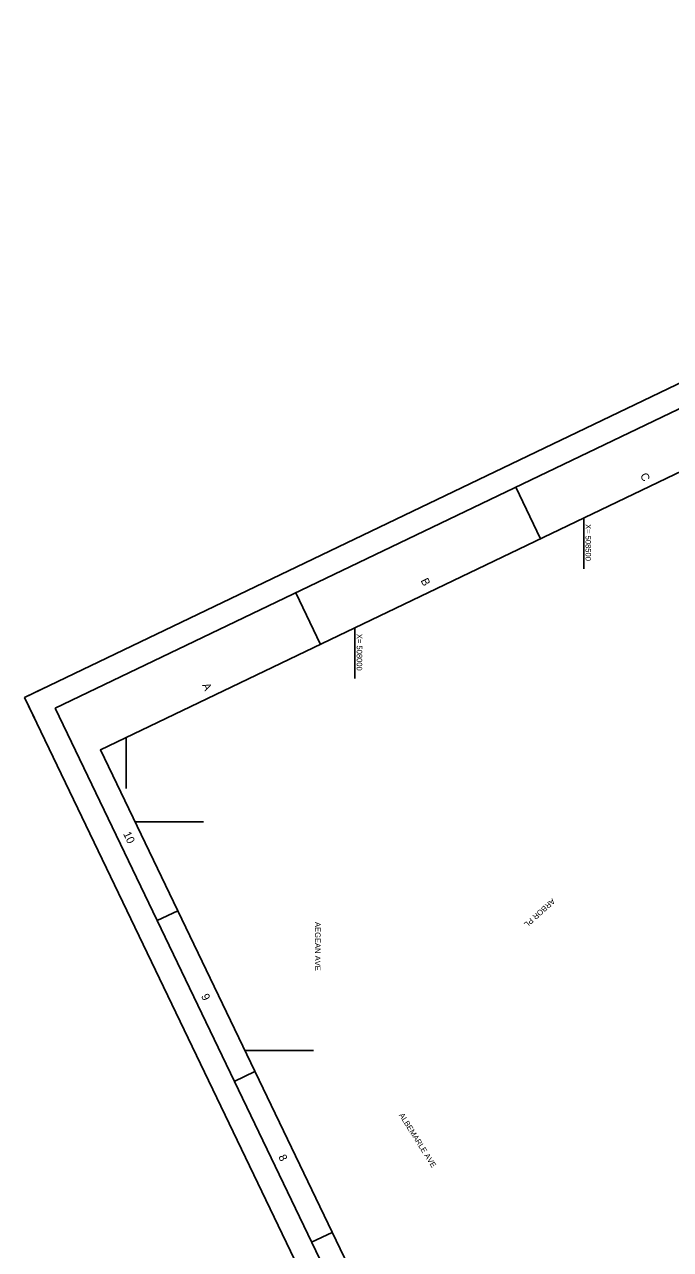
# Model space of a CAD drawing. Extents: x 507278 to 512248, y 1305805 to 1311243.
# Drawn here: x 507278 to 508690, y 1308565 to 1311243 of the extents above; entities that cross this region are included whole.
import ezdxf

# ---------------------------------------------------------------- set-up
doc = ezdxf.new("R2010")
doc.units = 0
for name, color, linetype in [('G-ANNO-NPLT', 7, 'Continuous'), ('G-ANNO-TTLB', 7, 'Continuous'), ('V-ROAD-IDEN', 7, 'Continuous'), ('V-TOPO-COOR-STAT', 7, 'Continuous')]:
    doc.layers.add(name, color=color, linetype=linetype)

msp = doc.modelspace()

# ---------------------------------------------------------------- linework, layer by layer
at = {"layer": 'G-ANNO-NPLT'}
msp.add_lwpolyline([(510343.2, 1311243.3), (512247.6, 1307276.8), (509182.6, 1305805.3), (507278.2, 1309771.7)], close=True, dxfattribs=at)
msp.add_lwpolyline([(507323.3, 1309793.4), (507278.2, 1309771.7), (507299.8, 1309726.7)], dxfattribs=at)
at = {"layer": 'G-ANNO-TTLB'}
for p, q in [((508351.5, 1310231.6), (508405.6, 1310118.9)), ((507870.7, 1310000.8), (507924.8, 1309888.1)), ((507567.8, 1309284), (507612.9, 1309305.7)), ((507736.6, 1308932.5), (507781.7, 1308954.1)), ((507905.4, 1308580.9), (507950.5, 1308602.5))]:
    msp.add_line(p, q, dxfattribs=at)
for points in [[(507344.9, 1309748.3), (509206, 1305872), (512180.9, 1307300.3), (510319.8, 1311176.6)], [(512114.2, 1307323.7), (510328.8, 1311042.3), (507444.1, 1309657.3), (509229.5, 1305938.7)]]:
    msp.add_lwpolyline(points, close=True, dxfattribs=at)
at = {"layer": 'V-TOPO-COOR-STAT'}
for p, q in [((508500, 1310053.3), (508500, 1310164.2)), ((508000, 1309813.2), (508000, 1309924.2)), ((507500, 1309573.2), (507500, 1309684.1)), ((507669.3, 1309500), (507519.6, 1309500)), ((507909.4, 1309000), (507759.6, 1309000))]:
    msp.add_line(p, q, dxfattribs=at)

# ---------------------------------------------------------------- texts
at = {"layer": 'G-ANNO-TTLB'}
for s, p in [('C', (508622.8, 1310257.9)), ('B', (508143.3, 1310027.9)), ('A', (507665.9, 1309798.8)), ('10', (507493.3, 1309473.9)), ('9', (507663.6, 1309119.2)), ('8', (507832.3, 1308767.8))]:
    msp.add_text(s, height=17.5, rotation=295.6468, dxfattribs=at).set_placement(p)
at = {"layer": 'V-ROAD-IDEN'}
for s, rotation, p in [('ARBOR PL', 221.8798, (508430.9, 1309333.4)), ('AEGEAN AVE', 269.8413, (507913.1, 1309281.1)), ('ALBEMARLE AVE', 302.0189, (508095.9, 1308858.9))]:
    msp.add_text(s, height=12, rotation=rotation, dxfattribs=at).set_placement(p)
at = {"layer": 'V-TOPO-COOR-STAT'}
for s, p in [('X= 508500', (508504, 1310151.1)), ('X= 508000', (508004, 1309911))]:
    msp.add_text(s, height=12, rotation=270, dxfattribs=at).set_placement(p)

doc.saveas('drawing.dxf')
